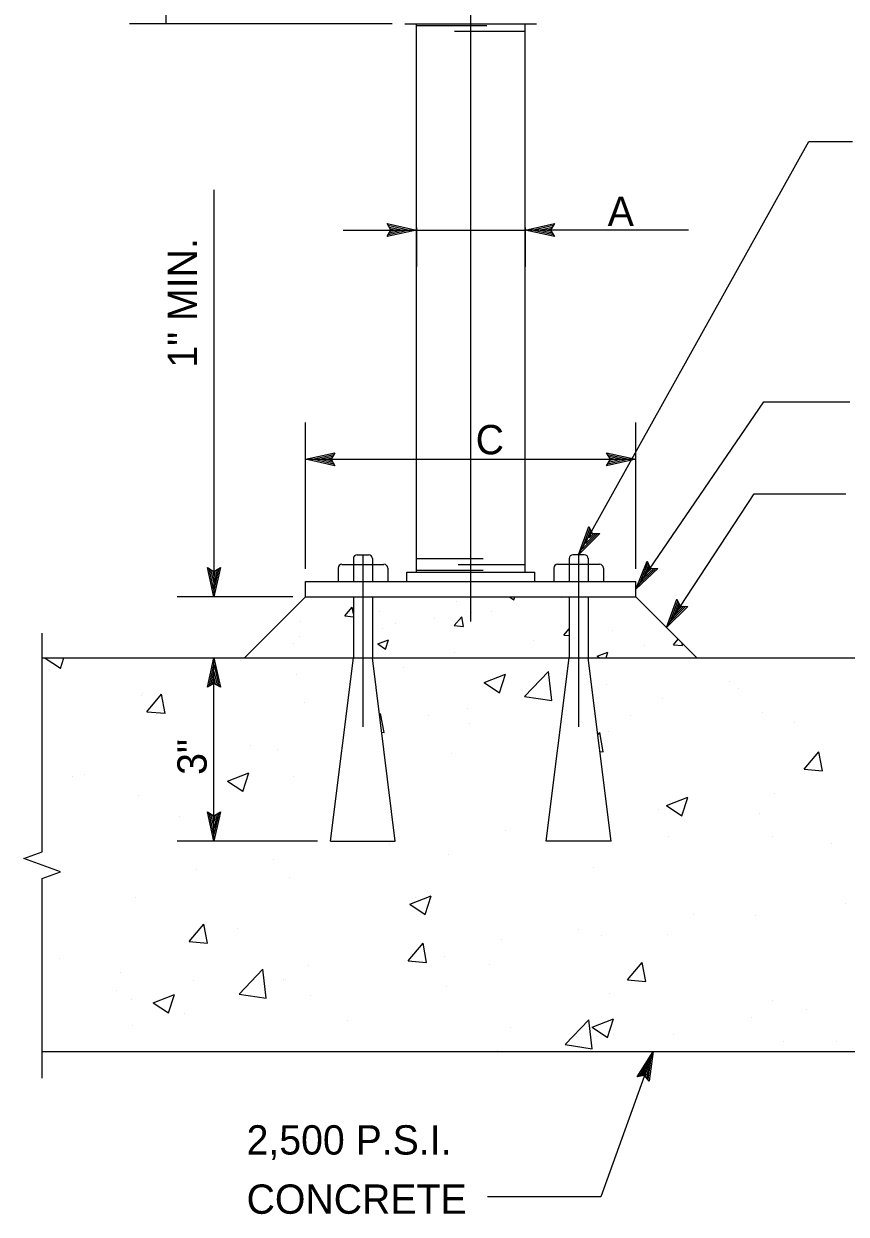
# Model space of a CAD drawing. Extents: x -123486 to -116575, y -107066 to -101122.
# Drawn here: x -117323.1 to -117154.8, y -102076.2 to -101832.8 of the extents above; entities that cross this region are included whole.
import ezdxf

# ---------------------------------------------------------------- set-up
doc = ezdxf.new("R2010")
doc.units = 0
for name, color, linetype in [('G-MARK', 7, 'Continuous'), ('G-TEXT', 7, 'Continuous'), ('Misc CnstDet(22)', 7, 'Continuous')]:
    doc.layers.add(name, color=color, linetype=linetype)

msp = doc.modelspace()

# ---------------------------------------------------------------- linework, layer by layer
at = {"layer": 'G-MARK'}
for p, q in [((-117293.95, -101832.76), (-117293.95, -101738.23)), ((-117247.75, -101832.76), (-117301.45, -101832.76)), ((-117284.19, -101866.71), (-117284.19, -101949.94)), ((-117257.78, -101874.94), (-117242.78, -101874.94)), ((-117187.08, -101874.94), (-117220.51, -101874.94)), ((-117265.44, -101944.19), (-117265.44, -101914.32)), ((-117197.86, -101944.19), (-117197.86, -101914.32)), ((-117265.44, -101921.82), (-117197.86, -101921.82)), ((-117268.06, -101949.94), (-117291.69, -101949.94)), ((-117284.19, -101999.94), (-117284.19, -101962.44)), ((-117262.98, -101999.94), (-117291.69, -101999.94))]:
    msp.add_line(p, q, dxfattribs=at)
for points in [[(-117209.58, -101941.35), (-117162.45, -101856.81), (-117153.54, -101856.81)], [(-117197.86, -101948.38), (-117171.69, -101910.1), (-117154.11, -101910.1)], [(-117191.61, -101956.19), (-117173.64, -101928.85), (-117154.89, -101928.85)], [(-117194.34, -102042.91), (-117205.05, -102072.63), (-117228.23, -102072.65)]]:
    msp.add_lwpolyline(points, dxfattribs=at)
at = {"layer": 'G-TEXT'}
for p, q in [((-117247.98, -101874.94), (-117248.78, -101873.6)), ((-117248.78, -101873.6), (-117248.78, -101873.6)), ((-117248.78, -101873.6), (-117242.78, -101874.94)), ((-117242.78, -101874.94), (-117248.78, -101876.27)), ((-117248.78, -101876.27), (-117247.98, -101874.94)), ((-117248.56, -101873.96), (-117244.16, -101874.94)), ((-117244.17, -101874.95), (-117248.55, -101875.91)), ((-117245.54, -101874.94), (-117248.37, -101875.57)), ((-117248.33, -101874.32), (-117245.54, -101874.94)), ((-117248.15, -101874.67), (-117246.92, -101874.94)), ((-117246.92, -101874.94), (-117248.13, -101875.21)), ((-117242.78, -101874.94), (-117242.78, -101874.94)), ((-117220.51, -101874.94), (-117214.51, -101873.61)), ((-117214.51, -101876.28), (-117220.51, -101874.94)), ((-117220.51, -101874.94), (-117220.51, -101874.94)), ((-117214.73, -101875.93), (-117219.13, -101874.94)), ((-117219.12, -101874.94), (-117214.75, -101873.97)), ((-117217.75, -101874.95), (-117214.93, -101874.32)), ((-117214.97, -101875.57), (-117217.75, -101874.95)), ((-117216.37, -101874.95), (-117215.16, -101874.68)), ((-117215.14, -101875.22), (-117216.37, -101874.95)), ((-117214.51, -101873.61), (-117215.31, -101874.94)), ((-117215.31, -101874.94), (-117214.51, -101876.28)), ((-117214.51, -101873.61), (-117214.51, -101873.61)), ((-117248.78, -101876.27), (-117248.78, -101876.27)), ((-117214.51, -101876.28), (-117214.51, -101876.28)), ((-117265.44, -101921.82), (-117259.44, -101920.49)), ((-117264.05, -101921.82), (-117259.67, -101920.85)), ((-117262.67, -101921.82), (-117259.85, -101921.19)), ((-117259.44, -101920.49), (-117260.24, -101921.82)), ((-117259.44, -101920.49), (-117259.44, -101920.49)), ((-117203.06, -101921.82), (-117203.86, -101920.48)), ((-117203.86, -101920.48), (-117203.86, -101920.48)), ((-117203.86, -101920.48), (-117197.86, -101921.82)), ((-117203.64, -101920.83), (-117199.24, -101921.82)), ((-117203.41, -101921.19), (-117200.62, -101921.82)), ((-117259.44, -101923.16), (-117265.44, -101921.82)), ((-117265.44, -101921.82), (-117265.44, -101921.82)), ((-117259.65, -101922.8), (-117264.06, -101921.82)), ((-117259.89, -101922.44), (-117262.67, -101921.82)), ((-117261.29, -101921.82), (-117260.08, -101921.55)), ((-117260.06, -101922.1), (-117261.29, -101921.82)), ((-117260.24, -101921.82), (-117259.44, -101923.16)), ((-117259.44, -101923.16), (-117259.44, -101923.16)), ((-117197.86, -101921.82), (-117203.86, -101923.15)), ((-117203.86, -101923.15), (-117203.06, -101921.82)), ((-117203.86, -101923.15), (-117203.86, -101923.15)), ((-117199.25, -101921.82), (-117203.62, -101922.79)), ((-117200.62, -101921.82), (-117203.45, -101922.44)), ((-117203.23, -101921.54), (-117202, -101921.82)), ((-117202, -101921.82), (-117203.21, -101922.08)), ((-117197.86, -101921.82), (-117197.86, -101921.82)), ((-117209.58, -101941.35), (-117207.48, -101935.57)), ((-117208.83, -101940.17), (-117207.3, -101935.96)), ((-117207.48, -101935.57), (-117207.48, -101935.57)), ((-117207.48, -101935.57), (-117206.79, -101936.96)), ((-117205.23, -101937.01), (-117209.58, -101941.35)), ((-117205.64, -101937), (-117208.84, -101940.19)), ((-117208.09, -101939.02), (-117207.11, -101936.3)), ((-117206.07, -101937), (-117208.09, -101939.02)), ((-117207.35, -101937.85), (-117206.93, -101936.69)), ((-117206.46, -101936.96), (-117207.35, -101937.85)), ((-117206.79, -101936.96), (-117205.23, -101937.01)), ((-117205.23, -101937.01), (-117205.23, -101937.01)), ((-117209.58, -101941.35), (-117209.58, -101941.35)), ((-117197.86, -101948.38), (-117195.57, -101942.68)), ((-117197.08, -101947.23), (-117195.41, -101943.07)), ((-117195.57, -101942.68), (-117195.57, -101942.68)), ((-117195.57, -101942.68), (-117194.92, -101944.09)), ((-117284.19, -101949.94), (-117285.52, -101943.94)), ((-117285.52, -101943.94), (-117285.52, -101943.94)), ((-117285.52, -101943.94), (-117284.19, -101944.74)), ((-117284.19, -101948.55), (-117285.16, -101944.18)), ((-117284.18, -101947.18), (-117284.81, -101944.36)), ((-117284.18, -101945.8), (-117284.45, -101944.59)), ((-117284.19, -101944.74), (-117282.85, -101943.94)), ((-117282.85, -101943.94), (-117284.19, -101949.94)), ((-117283.2, -101944.16), (-117284.19, -101948.56)), ((-117283.56, -101944.39), (-117284.18, -101947.18)), ((-117283.91, -101944.57), (-117284.18, -101945.8)), ((-117282.85, -101943.94), (-117282.85, -101943.94)), ((-117193.37, -101944.18), (-117197.86, -101948.38)), ((-117193.78, -101944.16), (-117197.08, -101947.24)), ((-117196.3, -101946.1), (-117195.22, -101943.42)), ((-117194.21, -101944.15), (-117196.3, -101946.1)), ((-117195.52, -101944.96), (-117195.06, -101943.81)), ((-117194.6, -101944.1), (-117195.52, -101944.96)), ((-117194.92, -101944.09), (-117193.37, -101944.18)), ((-117193.37, -101944.18), (-117193.37, -101944.18)), ((-117284.19, -101949.94), (-117284.19, -101949.94)), ((-117197.86, -101948.38), (-117197.86, -101948.38)), ((-117191.61, -101956.19), (-117189.45, -101950.44)), ((-117189.45, -101950.44), (-117189.45, -101950.44)), ((-117189.45, -101950.44), (-117188.77, -101951.84)), ((-117187.21, -101951.9), (-117191.61, -101956.19)), ((-117187.63, -101951.88), (-117190.86, -101955.04)), ((-117190.85, -101955.03), (-117189.28, -101950.83)), ((-117190.1, -101953.88), (-117189.08, -101951.17)), ((-117188.06, -101951.88), (-117190.1, -101953.88)), ((-117189.34, -101952.72), (-117188.91, -101951.56)), ((-117188.44, -101951.84), (-117189.34, -101952.72)), ((-117188.77, -101951.84), (-117187.21, -101951.9)), ((-117187.21, -101951.9), (-117187.21, -101951.9)), ((-117191.61, -101956.19), (-117191.61, -101956.19)), ((-117285.53, -101968.44), (-117284.19, -101962.44)), ((-117284.19, -101962.44), (-117284.19, -101962.44)), ((-117284.19, -101962.44), (-117282.86, -101968.44)), ((-117285.17, -101968.23), (-117284.19, -101963.82)), ((-117284.81, -101967.99), (-117284.19, -101965.21)), ((-117284.19, -101965.21), (-117283.56, -101968.03)), ((-117284.18, -101963.83), (-117283.22, -101968.21)), ((-117284.46, -101967.82), (-117284.19, -101966.59)), ((-117284.19, -101966.59), (-117283.92, -101967.8)), ((-117284.19, -101967.64), (-117285.53, -101968.44)), ((-117285.53, -101968.44), (-117285.53, -101968.44)), ((-117282.86, -101968.44), (-117284.19, -101967.64)), ((-117282.86, -101968.44), (-117282.86, -101968.44)), ((-117284.19, -101999.94), (-117285.52, -101993.94)), ((-117285.52, -101993.94), (-117285.52, -101993.94)), ((-117285.52, -101993.94), (-117284.19, -101994.74)), ((-117284.19, -101998.55), (-117285.16, -101994.18)), ((-117284.18, -101997.18), (-117284.81, -101994.36)), ((-117284.19, -101994.74), (-117282.85, -101993.94)), ((-117282.85, -101993.94), (-117284.19, -101999.94)), ((-117283.2, -101994.16), (-117284.19, -101998.56)), ((-117283.56, -101994.39), (-117284.18, -101997.18)), ((-117282.85, -101993.94), (-117282.85, -101993.94)), ((-117284.18, -101995.8), (-117284.45, -101994.59)), ((-117283.91, -101994.57), (-117284.18, -101995.8)), ((-117284.19, -101999.94), (-117284.19, -101999.94)), ((-117197.63, -102048.11), (-117194.34, -102042.91)), ((-117194.34, -102042.91), (-117195.12, -102049.01)), ((-117194.34, -102042.91), (-117194.34, -102042.91)), ((-117197.22, -102048.02), (-117194.81, -102044.21)), ((-117196.8, -102047.93), (-117195.28, -102045.51)), ((-117195.28, -102045.51), (-117195.64, -102048.38)), ((-117194.81, -102044.22), (-117195.38, -102048.67)), ((-117196.1, -102047.81), (-117197.63, -102048.11)), ((-117196.42, -102047.88), (-117195.75, -102046.81)), ((-117195.12, -102049.01), (-117196.1, -102047.81)), ((-117195.75, -102046.81), (-117195.9, -102048.04)), ((-117197.63, -102048.11), (-117197.63, -102048.11)), ((-117195.12, -102049.01), (-117195.12, -102049.01))]:
    msp.add_line(p, q, dxfattribs=at)
at = {"layer": 'Misc CnstDet(22)'}
for p, q in [((-117231.65, -101955.02), (-117231.65, -101695.26)), ((-117245.12, -101832.76), (-117218.17, -101832.76)), ((-117242.78, -101944.87), (-117242.78, -101832.76)), ((-117228.33, -101833.15), (-117242.78, -101833.15)), ((-117220.51, -101944.87), (-117220.51, -101832.76)), ((-117220.51, -101834.32), (-117234.97, -101834.32)), ((-117242.78, -101874.44), (-117242.78, -101882.44)), ((-117242.78, -101874.94), (-117220.51, -101874.94)), ((-117220.51, -101874.44), (-117220.51, -101882.44)), ((-117255.67, -101942.13), (-117255.67, -101946.82)), ((-117254.89, -101941.35), (-117252.55, -101941.35)), ((-117253.72, -101941.35), (-117253.72, -101976.51)), ((-117251.76, -101942.13), (-117251.76, -101946.82)), ((-117242.78, -101942.13), (-117229.11, -101942.13)), ((-117211.53, -101942.13), (-117211.53, -101946.82)), ((-117208.41, -101941.35), (-117210.75, -101941.35)), ((-117209.58, -101941.35), (-117209.58, -101976.51)), ((-117207.62, -101942.13), (-117207.62, -101946.82)), ((-117258.8, -101944.08), (-117258.8, -101946.82)), ((-117258.01, -101943.3), (-117249.42, -101943.3)), ((-117248.64, -101944.08), (-117248.64, -101946.82)), ((-117244.73, -101944.87), (-117218.56, -101944.87)), ((-117244.73, -101946.82), (-117244.73, -101944.87)), ((-117242.78, -101944.48), (-117229.11, -101944.48)), ((-117234.19, -101943.3), (-117220.51, -101943.3)), ((-117218.56, -101946.82), (-117218.56, -101944.87)), ((-117214.66, -101944.08), (-117214.66, -101946.82)), ((-117205.28, -101943.3), (-117213.87, -101943.3)), ((-117204.5, -101944.08), (-117204.5, -101946.82)), ((-117265.44, -101946.82), (-117197.86, -101946.82)), ((-117265.44, -101949.94), (-117265.44, -101946.82)), ((-117197.86, -101949.94), (-117197.86, -101946.82)), ((-117277.94, -101962.44), (-117265.44, -101949.94)), ((-117265.44, -101949.94), (-117197.86, -101949.94)), ((-117255.67, -101949.94), (-117255.67, -101962.44)), ((-117251.76, -101949.94), (-117251.76, -101962.44)), ((-117223.75, -101949.94), (-117222.86, -101950.54)), ((-117222.86, -101950.55), (-117222.65, -101949.94)), ((-117213.18, -101950.12), (-117213.18, -101950.12)), ((-117211.53, -101949.94), (-117211.53, -101962.44)), ((-117207.62, -101949.94), (-117207.62, -101962.44)), ((-117207.57, -101950.26), (-117207.57, -101950.26)), ((-117185.36, -101962.44), (-117197.86, -101949.94)), ((-117257.43, -101953.86), (-117255.92, -101952.07)), ((-117255.67, -101953.41), (-117255.92, -101952.07)), ((-117250.37, -101952.87), (-117250.37, -101952.87)), ((-117234.58, -101950.87), (-117234.58, -101950.87)), ((-117227.31, -101952.86), (-117227.31, -101952.86)), ((-117266.41, -101955.07), (-117266.41, -101955.07)), ((-117257.43, -101953.86), (-117255.67, -101954.02)), ((-117246.96, -101955.44), (-117246.96, -101955.44)), ((-117239.14, -101954.41), (-117239.14, -101954.41)), ((-117235.01, -101955.82), (-117233.5, -101954.03)), ((-117233.14, -101955.99), (-117233.5, -101954.03)), ((-117231.4, -101953.25), (-117231.4, -101953.25)), ((-117249.63, -101956.37), (-117249.63, -101956.37)), ((-117235.01, -101955.82), (-117233.14, -101955.99)), ((-117212.6, -101957.78), (-117211.53, -101956.51)), ((-117212.6, -101957.78), (-117211.53, -101957.88)), ((-117202.69, -101956.73), (-117202.69, -101956.73)), ((-117267.85, -101959.5), (-117267.85, -101959.5)), ((-117266.7, -101958.04), (-117266.7, -101958.04)), ((-117250.67, -101959.57), (-117248.48, -101958.73)), ((-117250.67, -101959.57), (-117249.12, -101960.62)), ((-117249.11, -101960.63), (-117248.48, -101958.74)), ((-117218.73, -101958.93), (-117218.73, -101958.93)), ((-117196.13, -101960), (-117196.13, -101960)), ((-117190.18, -101959.74), (-117189.21, -101958.59)), ((-117190.18, -101959.74), (-117188.31, -101959.91)), ((-117188.31, -101959.92), (-117188.41, -101959.39)), ((-117319.34, -101962.44), (-117132.62, -101962.44)), ((-117318.71, -101962.46), (-117318.67, -101962.44)), ((-117318.71, -101962.46), (-117315.6, -101964.56)), ((-117315.6, -101964.57), (-117314.89, -101962.44)), ((-117260.36, -101999.94), (-117255.67, -101962.44)), ((-117247.08, -101999.94), (-117251.76, -101962.44)), ((-117234.96, -101961.27), (-117234.96, -101961.27)), ((-117216.22, -101999.94), (-117211.53, -101962.44)), ((-117202.94, -101999.94), (-117207.62, -101962.44)), ((-117205.76, -101962.08), (-117203.57, -101961.24)), ((-117205.76, -101962.08), (-117205.21, -101962.44)), ((-117203.97, -101962.44), (-117203.57, -101961.24)), ((-117317.93, -101964.79), (-117317.93, -101964.79)), ((-117278.77, -101963.06), (-117278.77, -101963.06)), ((-117245.41, -101964.47), (-117245.41, -101964.47)), ((-117267.24, -101965.81), (-117267.24, -101965.81)), ((-117228.89, -101967.47), (-117224.52, -101965.79)), ((-117228.89, -101967.47), (-117225.78, -101969.56)), ((-117225.78, -101969.57), (-117224.51, -101965.79)), ((-117220.62, -101970.3), (-117215.76, -101965.23)), ((-117215.06, -101971.17), (-117215.75, -101965.24)), ((-117212.04, -101965.88), (-117212.04, -101965.88)), ((-117178.68, -101967.29), (-117178.68, -101967.29)), ((-117298.96, -101970.05), (-117298.96, -101970.05)), ((-117298.81, -101969.81), (-117298.81, -101969.81)), ((-117297.92, -101973.45), (-117294.91, -101969.85)), ((-117294.18, -101973.78), (-117294.9, -101969.86)), ((-117284.19, -101977.44), (-117284.19, -101969.94)), ((-117203.85, -101967.92), (-117203.85, -101967.92)), ((-117176.79, -101968.69), (-117176.79, -101968.69)), ((-117265.59, -101971.46), (-117265.59, -101971.46)), ((-117220.62, -101970.3), (-117215.06, -101971.17)), ((-117192.44, -101970.75), (-117192.44, -101970.75)), ((-117297.92, -101973.45), (-117294.18, -101973.77)), ((-117250.31, -101974.06), (-117250.08, -101973.78)), ((-117249.35, -101977.7), (-117250.08, -101973.78)), ((-117240.3, -101974.17), (-117240.3, -101974.17)), ((-117232.23, -101972.87), (-117232.23, -101972.87)), ((-117198.87, -101974.28), (-117198.87, -101974.28)), ((-117171.88, -101973.53), (-117171.88, -101973.53)), ((-117231.91, -101975.95), (-117231.91, -101975.95)), ((-117165.5, -101975.69), (-117165.5, -101975.69)), ((-117249.86, -101977.65), (-117249.35, -101977.69)), ((-117205.66, -101978.19), (-117205.25, -101977.7)), ((-117204.52, -101981.62), (-117205.25, -101977.71)), ((-117203.45, -101977.53), (-117203.45, -101977.53)), ((-117276.75, -101980.43), (-117276.75, -101980.43)), ((-117271.23, -101981.13), (-117271.23, -101981.13)), ((-117235.54, -101981.93), (-117235.54, -101981.93)), ((-117205.24, -101981.55), (-117204.53, -101981.62)), ((-117163.43, -101985.21), (-117160.42, -101981.62)), ((-117159.7, -101985.55), (-117160.42, -101981.63)), ((-117313.2, -101986.69), (-117313.2, -101986.69)), ((-117310.7, -101986.32), (-117310.7, -101986.32)), ((-117281.41, -101987.63), (-117277.03, -101985.95)), ((-117278.3, -101989.73), (-117277.03, -101985.95)), ((-117268, -101986.62), (-117268, -101986.62)), ((-117163.43, -101985.21), (-117159.7, -101985.54)), ((-117281.41, -101987.63), (-117278.3, -101989.72)), ((-117299.57, -101990.62), (-117299.57, -101990.62)), ((-117191.59, -101992.63), (-117187.21, -101990.95)), ((-117188.48, -101994.73), (-117187.21, -101990.96)), ((-117169.57, -101990.23), (-117169.57, -101990.23)), ((-117193.24, -101993.34), (-117193.24, -101993.34)), ((-117191.59, -101992.63), (-117188.48, -101994.73)), ((-117172.64, -101994.34), (-117172.64, -101994.34)), ((-117291.21, -101994.83), (-117291.21, -101994.83)), ((-117224.48, -101997.65), (-117224.48, -101997.65)), ((-117191.11, -101999.06), (-117191.11, -101999.06)), ((-117169.98, -101998.95), (-117169.98, -101998.95)), ((-117260.36, -101999.94), (-117247.08, -101999.94)), ((-117248.35, -102000.6), (-117248.35, -102000.6)), ((-117202.94, -101999.94), (-117216.22, -101999.94)), ((-117157.75, -102000.47), (-117157.75, -102000.47)), ((-117272.02, -102003.72), (-117272.02, -102003.72)), ((-117236.3, -102002.74), (-117236.3, -102002.74)), ((-117287.67, -102005.78), (-117287.67, -102005.78)), ((-117206.43, -102005.21), (-117206.43, -102005.21)), ((-117268.76, -102007.43), (-117268.76, -102007.43)), ((-117300.33, -102011.43), (-117300.33, -102011.43)), ((-117244.1, -102012.79), (-117239.72, -102011.11)), ((-117240.99, -102014.89), (-117239.72, -102011.12)), ((-117244.1, -102012.79), (-117240.99, -102014.89)), ((-117242.88, -102011.46), (-117242.88, -102011.46)), ((-117155.01, -102012.67), (-117155.01, -102012.67)), ((-117186.01, -102014.88), (-117186.01, -102014.88)), ((-117173.4, -102015.14), (-117173.4, -102015.14)), ((-117289.25, -102020.46), (-117286.23, -102016.87)), ((-117285.51, -102020.79), (-117286.23, -102016.87)), ((-117279.33, -102017.72), (-117279.33, -102017.72)), ((-117209.68, -102017.99), (-117209.68, -102017.99)), ((-117289.25, -102020.46), (-117285.51, -102020.78)), ((-117244.42, -102024.38), (-117241.4, -102020.79)), ((-117240.68, -102024.71), (-117241.4, -102020.8)), ((-117225.32, -102020.05), (-117225.32, -102020.05)), ((-117204.97, -102019.14), (-117204.97, -102019.14)), ((-117191.45, -102018.93), (-117191.45, -102018.93)), ((-117237.06, -102023.54), (-117237.06, -102023.54)), ((-117315.78, -102023.98), (-117315.78, -102023.98)), ((-117264.8, -102025.25), (-117264.8, -102025.25)), ((-117244.42, -102024.38), (-117240.68, -102024.71)), ((-117227.9, -102025.19), (-117227.9, -102025.19)), ((-117199.59, -102028.3), (-117196.58, -102024.71)), ((-117195.85, -102028.64), (-117196.57, -102024.72)), ((-117303.38, -102026.77), (-117303.38, -102026.77)), ((-117288.47, -102028.37), (-117288.47, -102028.37)), ((-117279.04, -102031.19), (-117274.17, -102026.11)), ((-117273.48, -102032.05), (-117274.17, -102026.12)), ((-117270.01, -102028.18), (-117270.01, -102028.18)), ((-117269.52, -102028.23), (-117269.52, -102028.23)), ((-117199.59, -102028.3), (-117195.85, -102028.63)), ((-117304.11, -102030.43), (-117304.11, -102030.43)), ((-117236.65, -102029.59), (-117236.65, -102029.59)), ((-117301.09, -102032.23), (-117301.09, -102032.23)), ((-117296.61, -102032.95), (-117292.24, -102031.27)), ((-117296.61, -102032.95), (-117293.5, -102035.04)), ((-117293.5, -102035.05), (-117292.24, -102031.27)), ((-117279.04, -102031.19), (-117273.48, -102032.05)), ((-117264.35, -102031.44), (-117264.35, -102031.44)), ((-117203.28, -102031), (-117203.28, -102031)), ((-117169.92, -102032.41), (-117169.92, -102032.41)), ((-117290.2, -102035.16), (-117290.2, -102035.16)), ((-117162.98, -102034.33), (-117162.98, -102034.33)), ((-117300.8, -102037.7), (-117300.8, -102037.7)), ((-117256.83, -102036.57), (-117256.83, -102036.57)), ((-117223.47, -102037.98), (-117223.47, -102037.98)), ((-117212.34, -102041.53), (-117207.47, -102036.46)), ((-117206.78, -102042.4), (-117207.47, -102036.46)), ((-117206.79, -102037.95), (-117202.42, -102036.27)), ((-117206.79, -102037.95), (-117203.68, -102040.05)), ((-117203.68, -102040.06), (-117202.42, -102036.28)), ((-117174.16, -102035.95), (-117174.16, -102035.95)), ((-117205.73, -102039.95), (-117205.73, -102039.95)), ((-117202.45, -102039.53), (-117202.45, -102039.53)), ((-117190.11, -102039.39), (-117190.11, -102039.39)), ((-117319.34, -102042.91), (-117132.62, -102042.91)), ((-117226.12, -102042.64), (-117226.12, -102042.64)), ((-117212.34, -102041.53), (-117206.78, -102042.39)), ((-117167.59, -102040.8), (-117167.59, -102040.8)), ((-117156.74, -102040.8), (-117156.74, -102040.8))]:
    msp.add_line(p, q, dxfattribs=at)
msp.add_lwpolyline([(-117319.34, -102048.38), (-117319.34, -102007.54), (-117315.59, -102006.17), (-117323.1, -102003.44), (-117319.34, -102002.07), (-117319.34, -101957.37)], dxfattribs=at)
for centre, start, end in [((-117254.89, -101942.13), 90, 180), ((-117252.55, -101942.13), 0, 90), ((-117210.75, -101942.13), 90, 180), ((-117208.41, -101942.13), 0, 90), ((-117258.01, -101944.08), 90, 180), ((-117249.42, -101944.08), 0, 90), ((-117213.87, -101944.08), 90, 180), ((-117205.28, -101944.08), 0, 90)]:
    msp.add_arc(centre, 0.781, start, end, dxfattribs=at)

# ---------------------------------------------------------------- texts
for s, p in [('A', (-117203.62, -101874.08)), ('C', (-117230.64, -101920.8)), ('2,500 P.S.I.', (-117277.51, -102064.01)), ('CONCRETE', (-117277.51, -102076.12))]:
    msp.add_text(s, height=6, dxfattribs=at).set_placement(p)
for s, p in [('1" MIN.', (-117287.64, -101903.07)), ('3"', (-117285.68, -101986.35))]:
    msp.add_text(s, height=6, rotation=90, dxfattribs=at).set_placement(p)

doc.saveas('drawing.dxf')
